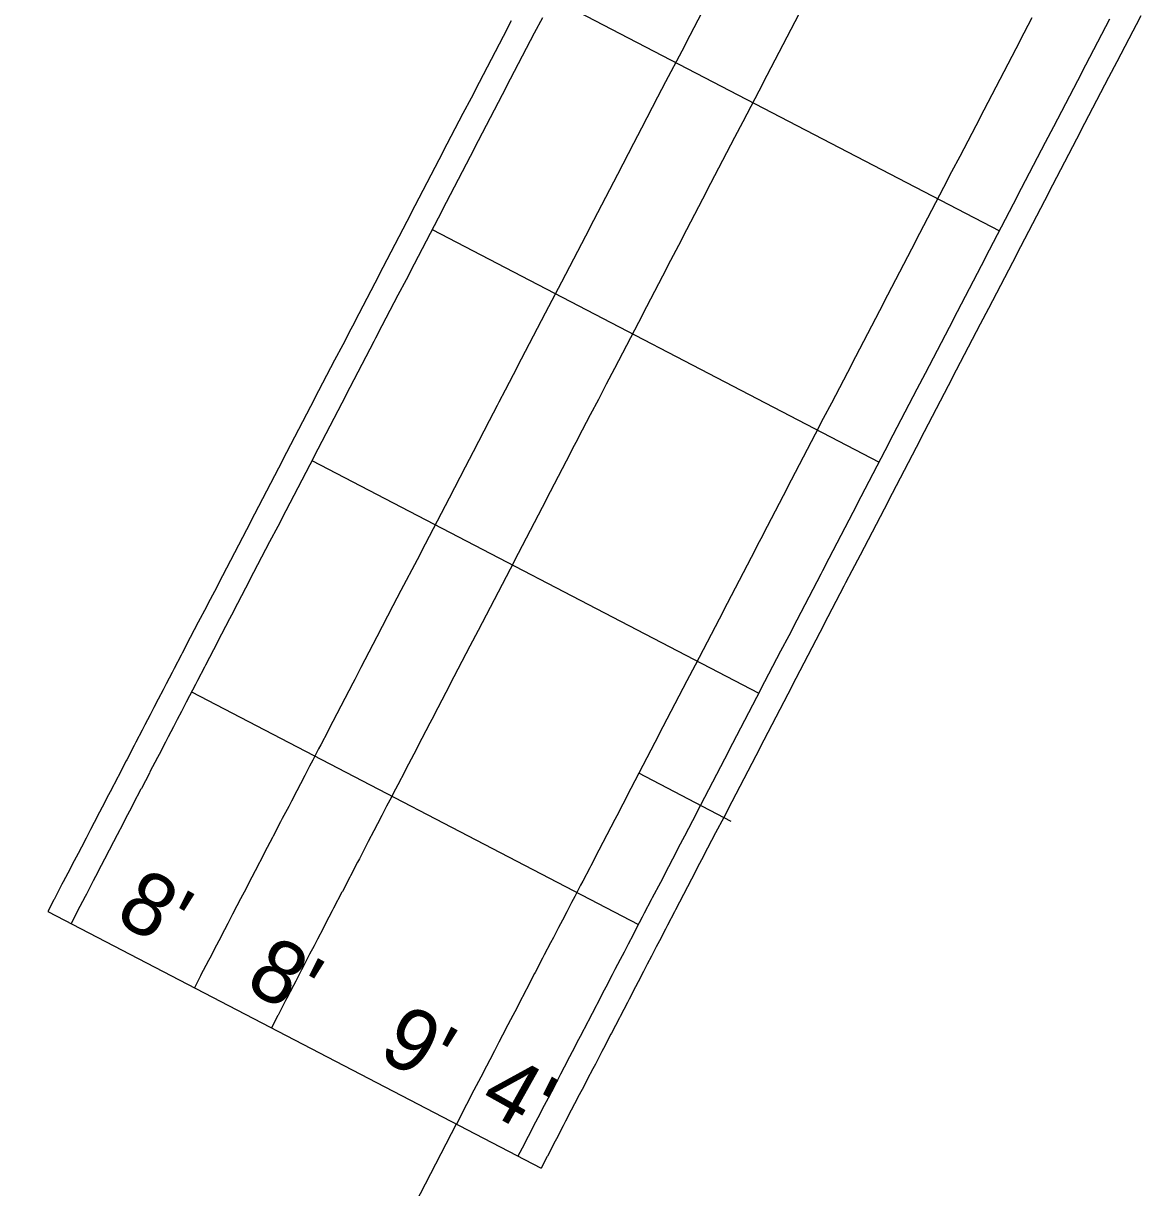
# Model space of a CAD drawing. Extents: x 2145147 to 2158018, y 137519 to 148068.
# Drawn here: x 2150352.7 to 2150417, y 143665.3 to 143732.3 of the extents above; entities that cross this region are included whole.
import ezdxf

# ---------------------------------------------------------------- set-up
doc = ezdxf.new("R2010")
doc.units = 0
for name, color, linetype in [('PR_Align_Ramp_B', 7, 'Continuous'), ('PR_Dimensions', 7, 'Continuous'), ('PR_Joint_Contraction', 7, 'Continuous'), ('PR_Joint_Long', 7, 'Continuous'), ('PR_Road_Concrete', 7, 'Continuous')]:
    doc.layers.add(name, color=color, linetype=linetype)

msp = doc.modelspace()

# ---------------------------------------------------------------- linework, layer by layer
at = {"layer": 'PR_Align_Ramp_B'}
msp.add_line((2150377.589, 143669.001), (2150332.794, 143582.93), dxfattribs=at)
msp.add_lwpolyline([(2150393.419, 143686.42), (2150388.097, 143689.19)], dxfattribs=at)
at = {"layer": 'PR_Joint_Contraction'}
for p, q in [((2150383.126, 143733.79), (2150408.847, 143720.403)), ((2150376.201, 143720.484), (2150401.922, 143707.097)), ((2150369.276, 143707.178), (2150394.997, 143693.791)), ((2150362.351, 143693.873), (2150388.072, 143680.486))]:
    msp.add_line(p, q, dxfattribs=at)
at = {"layer": 'PR_Joint_Long'}
for points in [[(2150391.946, 143733.407), (2150391.022, 143731.633), (2150390.561, 143730.746), (2150389.637, 143728.972), (2150389.176, 143728.085), (2150388.252, 143726.311), (2150387.791, 143725.424), (2150386.867, 143723.65), (2150386.406, 143722.763), (2150385.944, 143721.876), (2150385.482, 143720.988), (2150385.021, 143720.101), (2150384.097, 143718.327), (2150383.636, 143717.44), (2150382.712, 143715.666), (2150382.251, 143714.779), (2150381.327, 143713.005), (2150380.866, 143712.118), (2150380.404, 143711.232), (2150380.039, 143710.531), (2150379.942, 143710.345), (2150379.481, 143709.457), (2150378.557, 143707.683), (2150378.096, 143706.796), (2150377.172, 143705.022), (2150376.711, 143704.134), (2150375.787, 143702.36), (2150375.326, 143701.473), (2150374.402, 143699.699), (2150373.941, 143698.812), (2150373.017, 143697.038), (2150372.556, 143696.151), (2150372.094, 143695.265), (2150371.743, 143694.591), (2150371.632, 143694.377), (2150371.171, 143693.49), (2150370.247, 143691.717), (2150370.186, 143691.599), (2150369.785, 143690.828), (2150369.664, 143690.594), (2150369.324, 143689.943), (2150369.141, 143689.591), (2150368.862, 143689.056), (2150368.617, 143688.585), (2150368.4, 143688.167), (2150368.096, 143687.582), (2150367.939, 143687.281), (2150367.573, 143686.578), (2150367.476, 143686.392), (2150367.045, 143685.564), (2150367.011, 143685.498), (2150366.554, 143684.619), (2150366.528, 143684.569), (2150366.005, 143683.565), (2150365.632, 143682.848), (2150365.483, 143682.563), (2150365.169, 143681.958), (2150364.96, 143681.558), (2150364.707, 143681.071), (2150364.436, 143680.551), (2150364.246, 143680.184), (2150363.914, 143679.548), (2150363.783, 143679.296), (2150363.393, 143678.546), (2150363.323, 143678.412), (2150362.872, 143677.547), (2150362.863, 143677.529), (2150362.509, 143676.848)], [(2150397.304, 143732.872), (2150396.845, 143731.99), (2150396.38, 143731.098), (2150395.919, 143730.211), (2150395.46, 143729.329), (2150394.995, 143728.437), (2150394.534, 143727.55), (2150394.075, 143726.668), (2150393.61, 143725.776), (2150393.149, 143724.889), (2150392.69, 143724.007), (2150392.225, 143723.115), (2150391.764, 143722.228), (2150391.305, 143721.346), (2150390.839, 143720.452), (2150390.378, 143719.564), (2150389.92, 143718.684), (2150389.455, 143717.792), (2150388.994, 143716.905), (2150388.535, 143716.023), (2150388.07, 143715.131), (2150387.609, 143714.244), (2150387.15, 143713.362), (2150386.685, 143712.47), (2150386.224, 143711.583), (2150385.765, 143710.701), (2150385.3, 143709.809), (2150384.839, 143708.921), (2150384.478, 143708.228), (2150384.381, 143708.043), (2150383.915, 143707.148), (2150383.454, 143706.261), (2150382.995, 143705.379), (2150382.53, 143704.487), (2150382.068, 143703.598), (2150381.608, 143702.714), (2150381.145, 143701.825), (2150380.684, 143700.938), (2150380.225, 143700.056), (2150379.76, 143699.164), (2150379.299, 143698.277), (2150378.84, 143697.395), (2150378.375, 143696.503), (2150377.914, 143695.616), (2150377.455, 143694.734), (2150376.99, 143693.842), (2150376.529, 143692.955), (2150376.181, 143692.287), (2150376.07, 143692.074), (2150375.605, 143691.181), (2150375.144, 143690.294), (2150374.686, 143689.414), (2150374.625, 143689.297), (2150374.219, 143688.517), (2150374.095, 143688.279), (2150373.757, 143687.63), (2150373.578, 143687.285), (2150373.3, 143686.751), (2150373.056, 143686.282), (2150372.838, 143685.865), (2150372.522, 143685.258), (2150372.368, 143684.96), (2150372.007, 143684.268), (2150371.91, 143684.08), (2150371.491, 143683.275), (2150371.453, 143683.204), (2150371.03, 143682.39), (2150371.003, 143682.34), (2150370.527, 143681.424), (2150370.443, 143681.261), (2150370.068, 143680.542), (2150369.916, 143680.251), (2150369.601, 143679.642), (2150369.397, 143679.251), (2150369.145, 143678.768), (2150368.875, 143678.249), (2150368.684, 143677.882), (2150368.344, 143677.23), (2150368.215, 143676.979), (2150367.832, 143676.245), (2150367.763, 143676.112), (2150367.325, 143675.271), (2150367.314, 143675.25), (2150366.942, 143674.535)], [(2150410.719, 143732.656), (2150410.257, 143731.769), (2150409.795, 143730.881), (2150409.334, 143729.994), (2150408.872, 143729.107), (2150408.41, 143728.22), (2150407.949, 143727.333), (2150407.487, 143726.446), (2150407.025, 143725.559), (2150406.564, 143724.672), (2150406.102, 143723.785), (2150405.64, 143722.898), (2150405.179, 143722.011), (2150404.717, 143721.124), (2150404.255, 143720.237), (2150403.794, 143719.35), (2150403.332, 143718.463), (2150402.87, 143717.576), (2150402.409, 143716.689), (2150401.947, 143715.802), (2150401.485, 143714.915), (2150401.024, 143714.027), (2150400.562, 143713.14), (2150400.1, 143712.253), (2150399.639, 143711.366), (2150399.177, 143710.479), (2150398.715, 143709.592), (2150398.254, 143708.705), (2150397.792, 143707.818), (2150397.33, 143706.931), (2150396.869, 143706.044), (2150396.407, 143705.157), (2150395.945, 143704.27), (2150395.484, 143703.383), (2150395.119, 143702.682), (2150395.022, 143702.496), (2150394.56, 143701.609), (2150394.099, 143700.722), (2150393.637, 143699.835), (2150393.175, 143698.948), (2150392.714, 143698.061), (2150392.252, 143697.173), (2150391.79, 143696.286), (2150391.329, 143695.399), (2150390.867, 143694.512), (2150390.405, 143693.625), (2150389.944, 143692.738), (2150389.482, 143691.851), (2150389.02, 143690.964), (2150388.559, 143690.077), (2150388.097, 143689.19), (2150387.635, 143688.303), (2150387.174, 143687.416), (2150386.823, 143686.742), (2150386.712, 143686.529), (2150386.25, 143685.642), (2150385.789, 143684.755), (2150385.327, 143683.868), (2150385.266, 143683.751), (2150384.865, 143682.981), (2150384.743, 143682.746), (2150384.404, 143682.094), (2150384.221, 143681.742), (2150383.942, 143681.207), (2150383.698, 143680.738), (2150383.48, 143680.32), (2150383.175, 143679.734), (2150383.019, 143679.432), (2150382.653, 143678.73), (2150382.557, 143678.545), (2150382.13, 143677.725), (2150382.095, 143677.658), (2150381.634, 143676.771), (2150381.607, 143676.721), (2150381.172, 143675.884), (2150381.085, 143675.717), (2150380.71, 143674.997), (2150380.562, 143674.713), (2150380.249, 143674.11), (2150380.04, 143673.708), (2150379.787, 143673.223), (2150379.517, 143672.704), (2150379.325, 143672.336), (2150378.994, 143671.7), (2150378.864, 143671.449), (2150378.472, 143670.696), (2150378.402, 143670.562), (2150377.949, 143669.692), (2150377.94, 143669.675), (2150377.59, 143669.001)]]:
    msp.add_lwpolyline(points, dxfattribs=at)
at = {"layer": 'PR_Road_Concrete'}
msp.add_line((2150354.077, 143681.238), (2150382.471, 143666.46), dxfattribs=at)
for points in [[(2150380.743, 143732.474), (2150380.281, 143731.587), (2150379.82, 143730.7), (2150379.358, 143729.813), (2150378.896, 143728.926), (2150378.435, 143728.039), (2150377.973, 143727.152), (2150377.511, 143726.265), (2150377.05, 143725.378), (2150376.588, 143724.491), (2150376.126, 143723.603), (2150375.665, 143722.716), (2150375.203, 143721.829), (2150374.741, 143720.942), (2150374.28, 143720.055), (2150373.818, 143719.168), (2150373.356, 143718.281), (2150372.895, 143717.394), (2150372.433, 143716.507), (2150371.971, 143715.62), (2150371.607, 143714.919), (2150371.51, 143714.733), (2150371.048, 143713.846), (2150370.586, 143712.959), (2150370.125, 143712.072), (2150369.663, 143711.185), (2150369.201, 143710.298), (2150368.74, 143709.411), (2150368.278, 143708.524), (2150367.816, 143707.637), (2150367.355, 143706.75), (2150366.893, 143705.862), (2150366.431, 143704.975), (2150365.97, 143704.088), (2150365.508, 143703.201), (2150365.046, 143702.314), (2150364.585, 143701.427), (2150364.123, 143700.54), (2150363.661, 143699.653), (2150363.31, 143698.979), (2150363.2, 143698.766), (2150362.738, 143697.879), (2150362.276, 143696.992), (2150361.814, 143696.105), (2150361.754, 143695.988), (2150361.353, 143695.218), (2150361.231, 143694.984), (2150360.891, 143694.331), (2150360.708, 143693.979), (2150360.429, 143693.444), (2150360.186, 143692.975), (2150359.968, 143692.557), (2150359.663, 143691.971), (2150359.506, 143691.67), (2150359.14, 143690.967), (2150359.044, 143690.783), (2150358.618, 143689.962), (2150358.583, 143689.896), (2150358.121, 143689.008), (2150358.095, 143688.958), (2150357.659, 143688.121), (2150357.572, 143687.954), (2150357.198, 143687.234), (2150357.05, 143686.95), (2150356.736, 143686.347), (2150356.527, 143685.946), (2150356.274, 143685.46), (2150356.004, 143684.941), (2150355.813, 143684.573), (2150355.482, 143683.937), (2150355.351, 143683.686), (2150354.959, 143682.933), (2150354.889, 143682.799), (2150354.436, 143681.929), (2150354.428, 143681.912), (2150354.077, 143681.238)], [(2150382.541, 143732.665), (2150382.079, 143731.778), (2150381.618, 143730.891), (2150381.156, 143730.004), (2150380.694, 143729.117), (2150380.233, 143728.23), (2150379.771, 143727.343), (2150379.309, 143726.456), (2150378.848, 143725.569), (2150378.386, 143724.682), (2150377.924, 143723.795), (2150377.463, 143722.908), (2150377.001, 143722.021), (2150376.539, 143721.134), (2150376.078, 143720.247), (2150375.616, 143719.36), (2150375.154, 143718.473), (2150374.693, 143717.586), (2150374.231, 143716.699), (2150373.769, 143715.811), (2150373.308, 143714.924), (2150372.943, 143714.224), (2150372.846, 143714.037), (2150372.384, 143713.15), (2150371.923, 143712.263), (2150371.461, 143711.376), (2150370.999, 143710.489), (2150370.538, 143709.602), (2150370.076, 143708.715), (2150369.614, 143707.828), (2150369.153, 143706.941), (2150368.691, 143706.054), (2150368.229, 143705.167), (2150367.768, 143704.28), (2150367.306, 143703.393), (2150366.844, 143702.506), (2150366.383, 143701.619), (2150365.921, 143700.732), (2150365.459, 143699.845), (2150364.998, 143698.958), (2150364.647, 143698.283), (2150364.536, 143698.07), (2150364.074, 143697.183), (2150363.613, 143696.296), (2150363.151, 143695.409), (2150363.09, 143695.292), (2150362.689, 143694.522), (2150362.567, 143694.288), (2150362.228, 143693.635), (2150362.045, 143693.284), (2150361.766, 143692.748), (2150361.522, 143692.28), (2150361.304, 143691.861), (2150360.999, 143691.275), (2150360.843, 143690.974), (2150360.477, 143690.271), (2150360.381, 143690.087), (2150359.954, 143689.267), (2150359.919, 143689.2), (2150359.458, 143688.313), (2150359.431, 143688.263), (2150358.996, 143687.426), (2150358.909, 143687.258), (2150358.534, 143686.539), (2150358.386, 143686.254), (2150358.073, 143685.652), (2150357.864, 143685.25), (2150357.611, 143684.765), (2150357.341, 143684.246), (2150357.149, 143683.878), (2150356.818, 143683.242), (2150356.688, 143682.991), (2150356.296, 143682.237), (2150356.226, 143682.104), (2150355.773, 143681.233), (2150355.764, 143681.216), (2150355.413, 143680.542)], [(2150415.187, 143732.585), (2150414.726, 143731.697), (2150414.264, 143730.81), (2150413.802, 143729.923), (2150413.341, 143729.036), (2150412.879, 143728.149), (2150412.417, 143727.262), (2150411.956, 143726.375), (2150411.494, 143725.488), (2150411.032, 143724.601), (2150410.571, 143723.714), (2150410.109, 143722.827), (2150409.647, 143721.94), (2150409.186, 143721.053), (2150408.724, 143720.166), (2150408.262, 143719.279), (2150407.801, 143718.392), (2150407.339, 143717.505), (2150406.877, 143716.618), (2150406.416, 143715.731), (2150405.954, 143714.843), (2150405.492, 143713.956), (2150405.031, 143713.069), (2150404.569, 143712.182), (2150404.107, 143711.295), (2150403.646, 143710.408), (2150403.184, 143709.521), (2150402.722, 143708.634), (2150402.261, 143707.747), (2150401.799, 143706.86), (2150401.337, 143705.973), (2150400.876, 143705.086), (2150400.414, 143704.199), (2150399.952, 143703.312), (2150399.491, 143702.425), (2150399.029, 143701.538), (2150398.664, 143700.837), (2150398.567, 143700.651), (2150398.106, 143699.764), (2150397.644, 143698.877), (2150397.182, 143697.99), (2150396.721, 143697.102), (2150396.259, 143696.215), (2150395.797, 143695.328), (2150395.336, 143694.441), (2150394.874, 143693.554), (2150394.412, 143692.667), (2150393.951, 143691.78), (2150393.489, 143690.893), (2150393.027, 143690.006), (2150392.566, 143689.119), (2150392.104, 143688.232), (2150391.642, 143687.345), (2150391.181, 143686.458), (2150390.719, 143685.571), (2150390.368, 143684.897), (2150390.257, 143684.684), (2150389.796, 143683.797), (2150389.334, 143682.91), (2150388.872, 143682.023), (2150388.811, 143681.905), (2150388.411, 143681.136), (2150388.289, 143680.901), (2150387.949, 143680.248), (2150387.766, 143679.897), (2150387.487, 143679.361), (2150387.243, 143678.893), (2150387.026, 143678.474), (2150386.721, 143677.889), (2150386.564, 143677.587), (2150386.198, 143676.884), (2150386.102, 143676.7), (2150385.675, 143675.88), (2150385.641, 143675.813), (2150385.179, 143674.926), (2150385.153, 143674.876), (2150384.717, 143674.039), (2150384.63, 143673.872), (2150384.256, 143673.152), (2150384.107, 143672.868), (2150383.794, 143672.265), (2150383.585, 143671.863), (2150383.332, 143671.378), (2150383.062, 143670.859), (2150382.871, 143670.491), (2150382.54, 143669.855), (2150382.409, 143669.604), (2150382.017, 143668.851), (2150381.947, 143668.717), (2150381.494, 143667.846), (2150381.486, 143667.83), (2150381.135, 143667.156)], [(2150416.986, 143732.776), (2150416.718, 143732.262), (2150416.524, 143731.889), (2150416.062, 143731.002), (2150415.601, 143730.115), (2150415.139, 143729.228), (2150414.677, 143728.341), (2150414.216, 143727.454), (2150413.754, 143726.567), (2150413.292, 143725.68), (2150412.831, 143724.793), (2150412.369, 143723.905), (2150411.907, 143723.018), (2150411.446, 143722.131), (2150410.984, 143721.244), (2150410.522, 143720.357), (2150410.061, 143719.47), (2150409.599, 143718.583), (2150409.137, 143717.696), (2150408.676, 143716.809), (2150408.214, 143715.922), (2150407.752, 143715.035), (2150407.291, 143714.148), (2150406.829, 143713.261), (2150406.367, 143712.374), (2150405.905, 143711.487), (2150405.444, 143710.6), (2150404.982, 143709.713), (2150404.52, 143708.826), (2150404.059, 143707.939), (2150403.597, 143707.051), (2150403.135, 143706.164), (2150402.674, 143705.277), (2150402.212, 143704.39), (2150401.75, 143703.503), (2150401.289, 143702.616), (2150400.827, 143701.729), (2150400.365, 143700.842), (2150400.001, 143700.141), (2150399.904, 143699.955), (2150399.442, 143699.068), (2150398.98, 143698.181), (2150398.519, 143697.294), (2150398.057, 143696.407), (2150397.595, 143695.52), (2150397.134, 143694.633), (2150396.672, 143693.746), (2150396.21, 143692.859), (2150395.749, 143691.972), (2150395.287, 143691.085), (2150394.825, 143690.198), (2150394.364, 143689.31), (2150393.902, 143688.423), (2150393.44, 143687.536), (2150392.979, 143686.649), (2150392.517, 143685.762), (2150392.055, 143684.875), (2150391.705, 143684.201), (2150391.594, 143683.988), (2150391.132, 143683.101), (2150390.67, 143682.214), (2150390.209, 143681.327), (2150390.148, 143681.21), (2150389.747, 143680.44), (2150389.625, 143680.206), (2150389.285, 143679.553), (2150389.102, 143679.201), (2150388.824, 143678.666), (2150388.58, 143678.197), (2150388.362, 143677.779), (2150388.057, 143677.193), (2150387.9, 143676.892), (2150387.535, 143676.189), (2150387.439, 143676.005), (2150387.012, 143675.185), (2150386.977, 143675.118), (2150386.515, 143674.231), (2150386.489, 143674.18), (2150386.054, 143673.344), (2150385.967, 143673.176), (2150385.592, 143672.456), (2150385.444, 143672.172), (2150385.13, 143671.569), (2150384.921, 143671.168), (2150384.669, 143670.682), (2150384.399, 143670.164), (2150384.207, 143669.795), (2150383.876, 143669.159), (2150383.745, 143668.908), (2150383.353, 143668.155), (2150383.284, 143668.021), (2150382.831, 143667.151), (2150382.822, 143667.134), (2150382.471, 143666.46)]]:
    msp.add_lwpolyline(points, dxfattribs=at)

# ---------------------------------------------------------------- texts
at = {"layer": 'PR_Dimensions'}
for s, p in [("8'", (2150357.831, 143680.733)), ("8'", (2150365.318, 143676.84)), ("9'", (2150372.983, 143672.895)), ("4'", (2150378.782, 143670.019))]:
    msp.add_text(s, height=3.6, rotation=330.70293, dxfattribs=at).set_placement(p)

doc.saveas('drawing.dxf')
